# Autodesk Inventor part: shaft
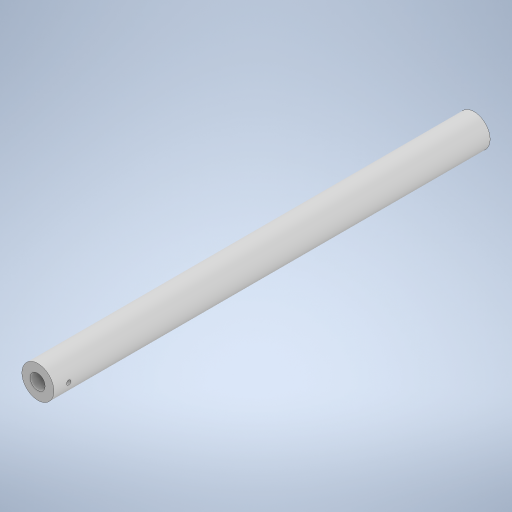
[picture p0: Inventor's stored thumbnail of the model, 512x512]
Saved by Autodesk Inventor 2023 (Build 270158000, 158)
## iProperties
Created: 2022-06
Part Number: shaft
Material: Generic
Document SubType Name: Modeling
Designer: prana_p9lsmih
Density: 1 g/cm^3
Appearance: Default
Author: prana_p9lsmih
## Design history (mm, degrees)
sketch "Sketch1"
  geometry: C1 r 7.5 at (0, 0); 1 further point
  constraints: 1 centre point, 1 coincident
  dimensions: "d0" = 15 diameter of C1
extrude "Extrusion1" new body sketch "Sketch1" distance "d1" = 205.029; taper "d2" = 0 deg
sketch "Sketch2"
  geometry: 2 further points
hole "Hole1" sketch "Sketch2" at (-0.127, -0.021) diameter "d3" = 7; stored, may be unused: countersink angle "d7" = 90 deg, drill point angle "d9" = 118 deg; dims "d4" = 6, "d5" = 4, "d6" = 2, "d8" = 10
workplane "Work Plane1"
sketch "Sketch3"
  geometry: L1 (7.5, 205.029)-(-7.5, 205.029) reference; C1 r 1 at (0, 198.029); 1 further point
  constraints: 1 centre point
  dimensions: "d10" = 2 diameter of C1; "d11" = 7 distance from line of C1.centre L1
extrude "Extrusion2" cut sketch "Sketch3" extent not by distance; stored distance "d12" = 0; taper "d13" = 0 deg
body "Solid1"
